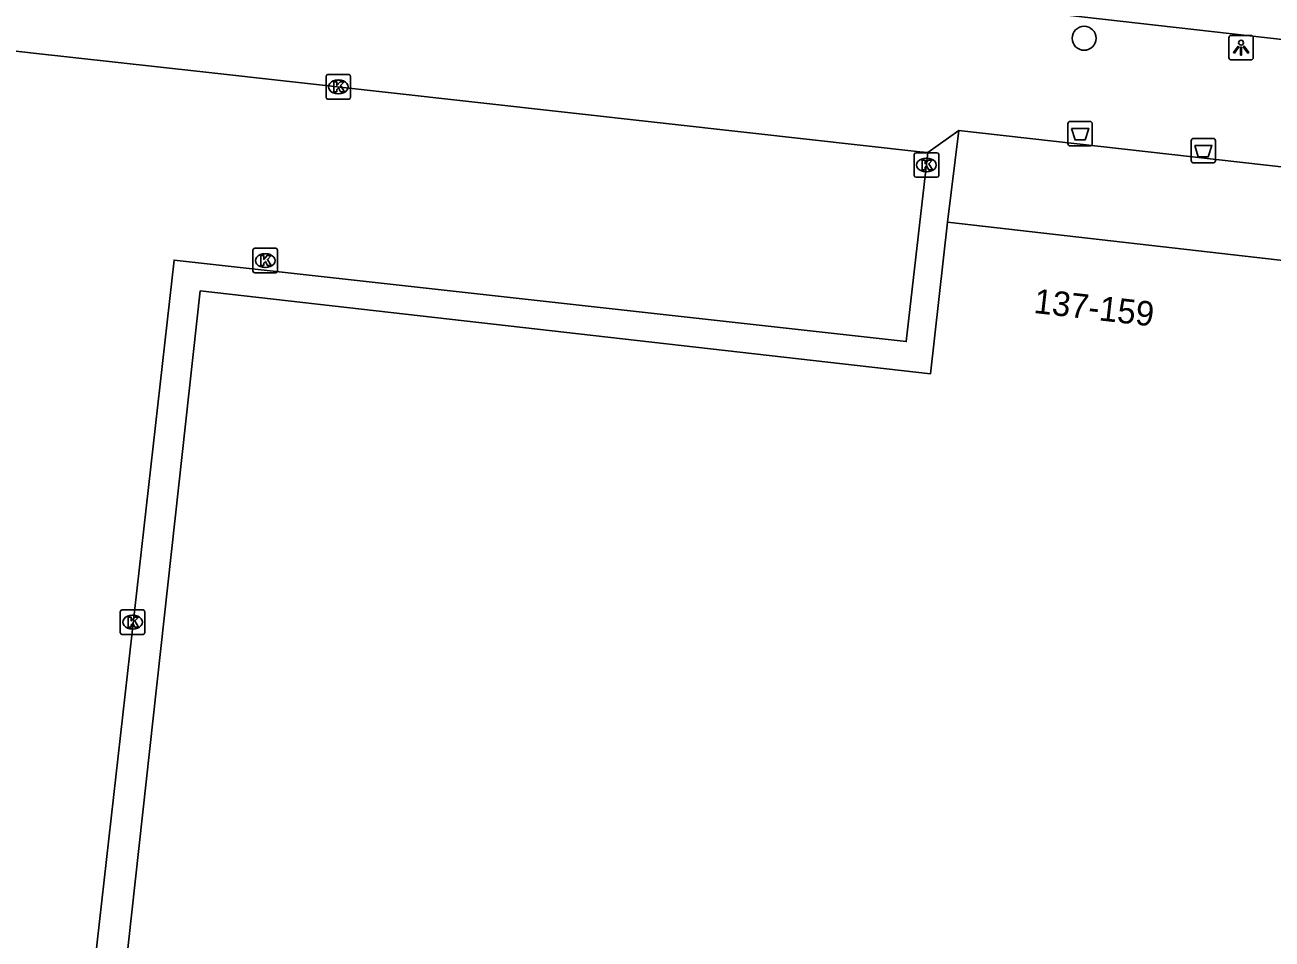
# Model space of a CAD drawing. Extents: x 161928 to 163055, y 386475 to 387428.
# Drawn here: x 162391.5 to 162442.3, y 386788 to 386825.3 of the extents above; entities that cross this region are included whole.
import ezdxf

# ---------------------------------------------------------------- set-up
doc = ezdxf.new("R2010")
doc.units = 0
for name, color, linetype in [('IMGEO_Afvalbak', 7, 'Continuous'), ('IMGEO_Boom', 7, 'Continuous'), ('IMGEO_Kolk', 7, 'Continuous'), ('IMGEO_Lichtpunt', 7, 'Continuous'), ('IMGEO_Pand', 7, 'Continuous'), ('IMGEO_Pand_nummerreeks', 7, 'Continuous'), ('IMGEO_Pand_overbouw', 7, 'Continuous'), ('IMGEO_Rijbaan_lokaal_open', 7, 'Continuous'), ('IMGEO_Voetpad_open', 7, 'Continuous')]:
    doc.layers.add(name, color=color, linetype=linetype)

msp = doc.modelspace()

# ---------------------------------------------------------------- linework, layer by layer
at = {"layer": 'IMGEO_Afvalbak'}
for p, q in [((162434.006, 386820.47), (162434.006, 386821.27)), ((162434.006, 386821.27), (162434.006, 386820.47)), ((162434.106, 386821.37), (162434.896, 386821.37)), ((162434.896, 386821.37), (162434.106, 386821.37)), ((162434.996, 386821.27), (162434.996, 386820.47)), ((162434.996, 386820.47), (162434.996, 386821.27)), ((162439.031, 386819.777), (162439.031, 386820.577)), ((162439.031, 386820.577), (162439.031, 386819.777)), ((162439.131, 386820.677), (162439.921, 386820.677)), ((162439.921, 386820.677), (162439.131, 386820.677)), ((162440.021, 386820.577), (162440.021, 386819.777)), ((162440.021, 386819.777), (162440.021, 386820.577)), ((162434.896, 386820.37), (162434.106, 386820.37)), ((162434.106, 386820.37), (162434.896, 386820.37)), ((162439.921, 386819.677), (162439.131, 386819.677)), ((162439.131, 386819.677), (162439.921, 386819.677))]:
    msp.add_line(p, q, dxfattribs=at)
for points in [[(162434.149, 386821.084), (162434.853, 386821.084), (162434.704, 386820.614), (162434.298, 386820.614), (162434.149, 386821.084)], [(162439.174, 386820.391), (162439.878, 386820.391), (162439.729, 386819.921), (162439.323, 386819.921), (162439.174, 386820.391)]]:
    msp.add_lwpolyline(points, dxfattribs=at)
for centre, start, end in [((162434.106, 386821.27), 90, 180), ((162434.106, 386821.27), 90, 180), ((162434.896, 386821.27), 0, 90), ((162434.896, 386821.27), 360, 90), ((162439.131, 386820.577), 90, 180), ((162439.131, 386820.577), 90, 180), ((162439.921, 386820.577), 0, 90), ((162439.921, 386820.577), 360, 90), ((162434.106, 386820.47), 180, 270), ((162434.106, 386820.47), 180, 270), ((162434.896, 386820.47), 270, 0), ((162434.896, 386820.47), 270, 0), ((162439.131, 386819.777), 180, 270), ((162439.131, 386819.777), 180, 270), ((162439.921, 386819.777), 270, 0), ((162439.921, 386819.777), 270, 0)]:
    msp.add_arc(centre, 0.1, start, end, dxfattribs=at)
at = {"layer": 'IMGEO_Boom'}
msp.add_circle((162434.665, 386824.758), 0.489, dxfattribs=at)
at = {"layer": 'IMGEO_Kolk'}
for p, q in [((162403.757, 386822.351), (162403.757, 386823.203)), ((162403.832, 386823.277), (162404.684, 386823.277)), ((162404.758, 386823.203), (162404.758, 386822.351)), ((162404.245, 386823.057), (162404.27, 386823.057)), ((162404.684, 386822.277), (162403.832, 386822.277)), ((162404.268, 386822.497), (162404.243, 386822.497)), ((162427.812, 386820.091), (162428.664, 386820.091)), ((162427.737, 386819.165), (162427.737, 386820.017)), ((162428.225, 386819.871), (162428.25, 386819.871)), ((162428.738, 386820.017), (162428.738, 386819.165)), ((162428.664, 386819.091), (162427.812, 386819.091)), ((162428.248, 386819.311), (162428.223, 386819.311)), ((162400.775, 386815.267), (162400.775, 386816.119)), ((162400.85, 386816.193), (162401.702, 386816.193)), ((162401.263, 386815.973), (162401.288, 386815.973)), ((162401.776, 386816.119), (162401.776, 386815.267)), ((162401.702, 386815.193), (162400.85, 386815.193)), ((162401.286, 386815.413), (162401.261, 386815.413)), ((162395.367, 386800.521), (162395.367, 386801.373)), ((162395.442, 386801.447), (162396.294, 386801.447)), ((162395.855, 386801.227), (162395.88, 386801.227)), ((162396.368, 386801.373), (162396.368, 386800.521)), ((162396.294, 386800.447), (162395.442, 386800.447)), ((162395.878, 386800.667), (162395.853, 386800.667))]:
    msp.add_line(p, q, dxfattribs=at)
for points in [[(162403.757, 386822.351), (162403.757, 386823.203)], [(162403.832, 386823.277), (162404.684, 386823.277)], [(162404.758, 386823.203), (162404.758, 386822.351)], [(162404.078, 386822.977), (162404.201, 386822.977), (162404.201, 386822.826), (162404.331, 386822.977), (162404.495, 386822.977), (162404.349, 386822.826), (162404.502, 386822.577), (162404.35, 386822.577), (162404.265, 386822.741), (162404.201, 386822.674), (162404.201, 386822.577), (162404.078, 386822.577), (162404.078, 386822.977)], [(162404.684, 386822.277), (162403.832, 386822.277)], [(162427.812, 386820.091), (162428.664, 386820.091)], [(162427.737, 386819.165), (162427.737, 386820.017)], [(162428.058, 386819.791), (162428.181, 386819.791), (162428.181, 386819.64), (162428.311, 386819.791), (162428.475, 386819.791), (162428.329, 386819.64), (162428.482, 386819.391), (162428.33, 386819.391), (162428.245, 386819.555), (162428.181, 386819.488), (162428.181, 386819.391), (162428.058, 386819.391), (162428.058, 386819.791)], [(162428.738, 386820.017), (162428.738, 386819.165)], [(162428.664, 386819.091), (162427.812, 386819.091)], [(162400.775, 386815.267), (162400.775, 386816.119)], [(162400.85, 386816.193), (162401.702, 386816.193)], [(162401.776, 386816.119), (162401.776, 386815.267)], [(162401.096, 386815.893), (162401.219, 386815.893), (162401.219, 386815.742), (162401.349, 386815.893), (162401.513, 386815.893), (162401.367, 386815.742), (162401.52, 386815.493), (162401.368, 386815.493), (162401.283, 386815.657), (162401.219, 386815.59), (162401.219, 386815.493), (162401.096, 386815.493), (162401.096, 386815.893)], [(162401.702, 386815.193), (162400.85, 386815.193)], [(162395.367, 386800.521), (162395.367, 386801.373)], [(162395.442, 386801.447), (162396.294, 386801.447)], [(162396.368, 386801.373), (162396.368, 386800.521)], [(162395.688, 386801.147), (162395.811, 386801.147), (162395.811, 386800.996), (162395.941, 386801.147), (162396.105, 386801.147), (162395.959, 386800.996), (162396.112, 386800.747), (162395.96, 386800.747), (162395.875, 386800.911), (162395.811, 386800.844), (162395.811, 386800.747), (162395.688, 386800.747), (162395.688, 386801.147)], [(162396.294, 386800.447), (162395.442, 386800.447)]]:
    msp.add_lwpolyline(points, dxfattribs=at)
for centre, start, end in [((162403.834, 386823.201), 91.552, 178.448), ((162403.834, 386823.201), 91.552, 178.448), ((162404.682, 386823.201), 1.552, 88.448), ((162404.682, 386823.201), 1.552, 88.448), ((162403.834, 386822.353), 181.552, 268.448), ((162403.834, 386822.353), 181.552, 268.448), ((162404.682, 386822.353), 271.552, 358.448), ((162404.682, 386822.353), 271.552, 358.448), ((162427.814, 386820.015), 91.552, 178.448), ((162427.814, 386820.015), 91.552, 178.448), ((162428.662, 386820.015), 1.552, 88.448), ((162428.662, 386820.015), 1.552, 88.448), ((162427.814, 386819.167), 181.552, 268.448), ((162427.814, 386819.167), 181.552, 268.448), ((162428.662, 386819.167), 271.552, 358.448), ((162428.662, 386819.167), 271.552, 358.448), ((162400.852, 386816.117), 91.552, 178.448), ((162400.852, 386816.117), 91.552, 178.448), ((162401.7, 386816.117), 1.552, 88.448), ((162401.7, 386816.117), 1.552, 88.448), ((162400.852, 386815.269), 181.552, 268.448), ((162400.852, 386815.269), 181.552, 268.448), ((162401.7, 386815.269), 271.552, 358.448), ((162401.7, 386815.269), 271.552, 358.448), ((162395.444, 386801.371), 91.552, 178.448), ((162395.444, 386801.371), 91.552, 178.448), ((162396.292, 386801.371), 1.552, 88.448), ((162396.292, 386801.371), 1.552, 88.448), ((162395.444, 386800.523), 181.552, 268.448), ((162395.444, 386800.523), 181.552, 268.448), ((162396.292, 386800.523), 271.552, 358.448), ((162396.292, 386800.523), 271.552, 358.448)]:
    msp.add_arc(centre, 0.0765, start, end, dxfattribs=at)
for centre, major_axis, ratio, start_param, end_param in [((162404.244, 386822.777), (-0.387, 0.002), 0.722429, 4.712389, 7.853982), ((162404.269, 386822.777), (-0.39, 0.002), 0.717154, 1.570796, 4.712389), ((162428.224, 386819.591), (-0.387, 0.002), 0.722429, 4.712389, 7.853982), ((162428.249, 386819.591), (-0.39, 0.002), 0.717154, 1.570796, 4.712389), ((162401.262, 386815.693), (-0.387, 0.002), 0.722429, 4.712389, 7.853982), ((162401.287, 386815.693), (-0.39, 0.002), 0.717154, 1.570796, 4.712389), ((162395.854, 386800.947), (-0.387, 0.002), 0.722429, 4.712389, 7.853982), ((162395.879, 386800.947), (-0.39, 0.002), 0.717154, 1.570796, 4.712389)]:
    msp.add_ellipse(centre, major_axis=major_axis, ratio=ratio, start_param=start_param, end_param=end_param, dxfattribs=at)
at = {"layer": 'IMGEO_Lichtpunt'}
for p, q in [((162440.567, 386824.779), (162440.567, 386823.972)), ((162440.567, 386824.779), (162440.567, 386823.972)), ((162441.469, 386824.874), (162440.661, 386824.874)), ((162441.469, 386824.874), (162440.661, 386824.874)), ((162441.563, 386823.972), (162441.563, 386824.779)), ((162441.563, 386823.972), (162441.563, 386824.779)), ((162440.661, 386823.878), (162441.469, 386823.878)), ((162440.661, 386823.878), (162441.469, 386823.878))]:
    msp.add_line(p, q, dxfattribs=at)
for points in [[(162440.941, 386824.443), (162440.98, 386824.415), (162440.792, 386824.153), (162440.754, 386824.18), (162440.941, 386824.443)], [(162441.043, 386824.395), (162441.09, 386824.395), (162441.09, 386824.073), (162441.043, 386824.073), (162441.043, 386824.395)], [(162441.153, 386824.415), (162441.191, 386824.442), (162441.378, 386824.18), (162441.339, 386824.152), (162441.153, 386824.415)]]:
    msp.add_lwpolyline(points, dxfattribs=at)
msp.add_circle((162441.066, 386824.577), 0.0994, dxfattribs=at)
for centre, start, end in [((162440.661, 386824.779), 90, 180), ((162440.661, 386824.779), 90, 180), ((162441.469, 386824.779), 0, 90), ((162441.469, 386824.779), 0, 90), ((162440.661, 386823.972), 180, 270), ((162440.661, 386823.972), 180, 270), ((162441.469, 386823.972), 270, 0), ((162441.469, 386823.972), 270, 360)]:
    msp.add_arc(centre, 0.0946, start, end, dxfattribs=at)
at = {"layer": 'IMGEO_Pand'}
for points in [[(162444.943, 386759.093), (162393.168, 386764.919), (162394.363, 386775.766), (162398.627, 386814.456), (162428.397, 386811.07), (162429.101, 386817.257)], [(162463.923, 386814.853), (162444.241, 386816.845), (162444.094, 386815.551), (162429.101, 386817.257)]]:
    msp.add_lwpolyline(points, dxfattribs=at)
at = {"layer": 'IMGEO_Pand_overbouw'}
msp.add_lwpolyline([(162429.556, 386820.996), (162429.101, 386817.257), (162444.094, 386815.551), (162444.241, 386816.845), (162463.923, 386814.853), (162464.178, 386817.097)], close=True, dxfattribs=at)
at = {"layer": 'IMGEO_Rijbaan_lokaal_open'}
for points in [[(162428.69, 386826.295), (162472.053, 386821.397)], [(162428.297, 386820.095), (162427.973, 386820.131), (162421.03, 386820.904), (162398.609, 386823.401), (162391.827, 386824.156), (162389.799, 386824.382)], [(162428.297, 386820.095), (162427.417, 386812.392), (162397.559, 386815.714), (162394.424, 386787.899), (162394.088, 386784.654)]]:
    msp.add_lwpolyline(points, dxfattribs=at)
at = {"layer": 'IMGEO_Voetpad_open'}
for points in [[(162429.556, 386820.996), (162428.297, 386820.095)], [(162429.101, 386817.257), (162429.556, 386820.996)], [(162464.178, 386817.097), (162429.556, 386820.996)]]:
    msp.add_lwpolyline(points, dxfattribs=at)

# ---------------------------------------------------------------- texts
at = {"layer": 'IMGEO_Pand_nummerreeks'}
msp.add_text('137-159', height=1, rotation=353.5084, dxfattribs=at).set_placement((162432.581, 386813.56))

doc.saveas('drawing.dxf')
